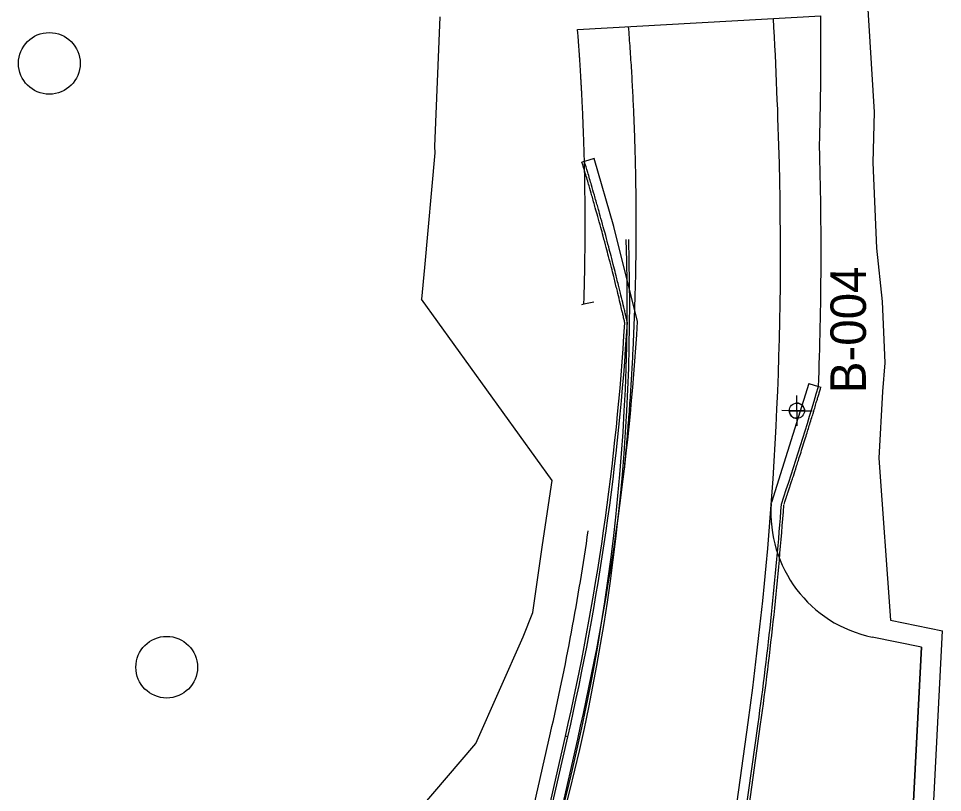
# Model space of a CAD drawing. Extents: x -14 to 1565148, y -25 to 642856.
# Drawn here: x 1564634.8 to 1564817, y 636708.2 to 636860.8 of the extents above; entities that cross this region are included whole.
import ezdxf

# ---------------------------------------------------------------- set-up
doc = ezdxf.new("R2010")
doc.units = 0
for name, color, linetype in [('_CIVIL_CONSTRUCTION', 7, 'Continuous'), ('DR_P_Drainage_Area', 7, 'Continuous'), ('DR_P_Erosion_Control', 7, 'Continuous'), ('GE_P_Alignment', 7, 'Continuous'), ('GE_X_Alignment', 7, 'Continuous'), ('PM_X_CL_Double_Solid', 7, 'Continuous'), ('PV_P_EOP', 7, 'Continuous'), ('PV_X_COP', 7, 'Continuous'), ('PV_X_EOP', 7, 'Continuous'), ('SC_Scratch10', 7, 'Continuous'), ('SC_Scratch15', 7, 'Continuous'), ('SC_Scratch2', 7, 'Continuous'), ('VG_P_Text', 7, 'Continuous')]:
    doc.layers.add(name, color=color, linetype=linetype)

msp = doc.modelspace()

# ---------------------------------------------------------------- linework, layer by layer
at = {"layer": '_CIVIL_CONSTRUCTION'}
for p, q in [((1564788.32, 636783.45), (1564788.33, 636786.45)), ((1564788.32, 636783.45), (1564788.32, 636784.95)), ((1564788.32, 636783.45), (1564785.32, 636783.46)), ((1564786.82, 636783.45), (1564788.32, 636783.45)), ((1564788.32, 636783.45), (1564791.32, 636783.45)), ((1564788.32, 636783.45), (1564788.32, 636780.45)), ((1564789.82, 636783.45), (1564788.32, 636783.45)), ((1564788.32, 636783.45), (1564788.32, 636781.95))]:
    msp.add_line(p, q, dxfattribs=at)
msp.add_circle((1564788.32, 636783.45), 1.5, dxfattribs=at)
for start, end in [(359.94, 89.94), (179.94, 269.94)]:
    msp.add_arc((1564788.32, 636783.45), 1.5, start, end, dxfattribs=at)
at = {"layer": 'DR_P_Drainage_Area'}
for radius in [397.5, 398]:
    msp.add_arc((1564357.36, 636804.71), radius, 342.3578, 1.7978, dxfattribs=at)
at = {"layer": 'DR_P_Erosion_Control'}
msp.add_open_spline([(1564754.31, 636771.87), (1564754.45, 636773.32), (1564754.72, 636776.23), (1564755.08, 636780.59), (1564755.41, 636784.95), (1564755.7, 636789.32), (1564755.95, 636793.69), (1564756.16, 636798.06), (1564756.33, 636802.43), (1564756.47, 636806.8), (1564756.57, 636811.17), (1564756.63, 636815.55), (1564756.65, 636819.92), (1564756.64, 636824.29), (1564756.58, 636828.66), (1564756.49, 636833.02), (1564756.36, 636837.39), (1564756.2, 636841.75), (1564755.99, 636846.11), (1564755.75, 636850.47), (1564755.47, 636854.83), (1564755.25, 636857.73), (1564755.14, 636859.18)], degree=3, dxfattribs=at)
at = {"layer": 'GE_P_Alignment'}
msp.add_arc((1564110.09, 636814.7), 683, 357.77768, 1.74215, dxfattribs=at)
for points in [[(1564792.77, 636835.46), (1564792.79, 636835.89), (1564792.81, 636836.75), (1564792.85, 636838.04), (1564792.88, 636839.33), (1564792.91, 636840.62), (1564792.93, 636841.91), (1564792.96, 636843.2), (1564792.98, 636844.5), (1564793, 636845.79), (1564793.02, 636847.08), (1564793.03, 636848.37), (1564793.05, 636849.66), (1564793.06, 636850.95), (1564793.07, 636852.24), (1564793.07, 636853.53), (1564793.07, 636854.83), (1564793.07, 636856.12), (1564793.07, 636857.41), (1564793.07, 636858.7), (1564793.06, 636859.99), (1564793.06, 636860.85), (1564793.05, 636861.29)], [(1564746.42, 636832.6), (1564746.39, 636834.11), (1564746.34, 636835.57), (1564746.26, 636837.91), (1564746.23, 636838.8), (1564746.16, 636840.59), (1564746.12, 636841.48), (1564746.04, 636843.26), (1564746, 636844.15), (1564745.93, 636845.49), (1564745.91, 636845.93), (1564745.86, 636846.83), (1564745.82, 636847.72), (1564745.76, 636848.61), (1564745.71, 636849.5), (1564745.69, 636849.95), (1564745.61, 636851.28), (1564745.55, 636852.17), (1564745.47, 636853.28), (1564745.46, 636853.5), (1564745.43, 636853.95), (1564745.41, 636854.17), (1564745.37, 636854.83), (1564745.34, 636855.28), (1564745.24, 636856.62), (1564745.17, 636857.52), (1564745.09, 636858.62)]]:
    msp.add_open_spline(points, degree=3, dxfattribs=at)
at = {"layer": 'GE_X_Alignment'}
msp.add_lwpolyline([(1564800.19, 636706.05), (1564811.23, 636705.19), (1564812.86, 636736.84), (1564811.23, 636705.19), (1564800.19, 636706.05)], dxfattribs=at)
at = {"layer": 'PM_X_CL_Double_Solid'}
for p, q in [((1564746.32, 636804.45), (1564745.83, 636804.34)), ((1564748.28, 636804.85), (1564746.32, 636804.45))]:
    msp.add_line(p, q, dxfattribs=at)
msp.add_open_spline([(1564746.32, 636804.45), (1564746.32, 636804.6), (1564746.33, 636804.74), (1564746.45, 636808.46), (1564746.52, 636812.03), (1564746.59, 636819.17), (1564746.58, 636822.74), (1564746.51, 636828.41), (1564746.47, 636830.51), (1564746.42, 636832.6)], degree=3, dxfattribs=at)
at = {"layer": 'PV_P_EOP'}
for p, q in [((1564746.42, 636832.6), (1564745.94, 636832.46)), ((1564792.58, 636788.22), (1564793.06, 636788.07)), ((1564773.12, 636667.28), (1564780.67, 636721.69)), ((1564778.16, 636699.96), (1564781.17, 636721.62)), ((1564731.52, 636670.52), (1564742.67, 636719.26)), ((1564732.01, 636670.41), (1564743.16, 636719.15))]:
    msp.add_line(p, q, dxfattribs=at)
for centre, radius, start, end in [((1564252.82, 636831.29), 502.5, 347.1178, 356.5174), ((1564252.82, 636831.29), 503, 347.1178, 356.5263), ((1564144.31, 636979.68), 675.95, 341.48255, 343.54567), ((1564110.09, 636814.7), 677, 352.10361, 355.79015), ((1564110.09, 636814.7), 677.5, 352.10361, 355.77956)]:
    msp.add_arc(centre, radius, start, end, dxfattribs=at)
for points in [[(1564754.4, 636800.77), (1564754.37, 636800.89), (1564754.32, 636801.12), (1564754.2, 636801.63), (1564754.13, 636801.92), (1564753.92, 636802.83), (1564753.75, 636803.53), (1564753.23, 636805.72), (1564752.84, 636807.31), (1564752.13, 636810.17), (1564751.81, 636811.44), (1564751.14, 636814.04), (1564750.79, 636815.38), (1564750.08, 636818.05), (1564749.71, 636819.39), (1564749, 636821.97), (1564748.65, 636823.21), (1564747.85, 636826.03), (1564747.4, 636827.59), (1564746.56, 636830.44), (1564746.17, 636831.72), (1564745.94, 636832.46)], [(1564754.9, 636800.82), (1564754.87, 636800.94), (1564754.85, 636801.03), (1564754.8, 636801.24), (1564754.77, 636801.36), (1564754.68, 636801.75), (1564754.62, 636802.03), (1564754.4, 636802.95), (1564754.24, 636803.64), (1564753.72, 636805.84), (1564753.33, 636807.43), (1564752.62, 636810.29), (1564752.3, 636811.56), (1564751.62, 636814.17), (1564751.27, 636815.51), (1564750.56, 636818.18), (1564750.2, 636819.52), (1564749.48, 636822.1), (1564749.13, 636823.35), (1564748.33, 636826.16), (1564747.88, 636827.73), (1564747.04, 636830.58), (1564746.65, 636831.86), (1564746.42, 636832.6)], [(1564785.78, 636764.96), (1564785.86, 636765.2), (1564785.94, 636765.44), (1564786.1, 636765.92), (1564786.18, 636766.16), (1564786.42, 636766.88), (1564786.57, 636767.36), (1564786.89, 636768.32), (1564787.05, 636768.8), (1564787.36, 636769.76), (1564787.52, 636770.24), (1564788.3, 636772.64), (1564788.91, 636774.56), (1564790.13, 636778.41), (1564790.72, 636780.34), (1564791.61, 636783.24), (1564791.9, 636784.2), (1564792.26, 636785.41), (1564792.34, 636785.65), (1564792.48, 636786.14), (1564792.55, 636786.38), (1564792.7, 636786.86), (1564792.77, 636787.11), (1564792.91, 636787.59), (1564792.98, 636787.83), (1564793.06, 636788.07)]]:
    msp.add_open_spline(points, degree=3, dxfattribs=at)
at = {"layer": 'PV_X_COP'}
for p, q in [((1564812.86, 636736.84), (1564803.18, 636738.82)), ((1564811.23, 636705.19), (1564812.86, 636736.84))]:
    msp.add_line(p, q, dxfattribs=at)
msp.add_arc((1564808.2, 636763.31), 25, 175.7902, 258.4067, dxfattribs=at)
at = {"layer": 'PV_X_EOP'}
for p, q in [((1564745.09, 636858.62), (1564793.05, 636861.29)), ((1564748.34, 636833.16), (1564746.42, 636832.6)), ((1564790.67, 636788.82), (1564783.29, 636765.38)), ((1564790.67, 636788.82), (1564792.58, 636788.22)), ((1564771.14, 636667.56), (1564778.69, 636721.97)), ((1564733.96, 636669.96), (1564745.11, 636718.7))]:
    msp.add_line(p, q, dxfattribs=at)
msp.add_lwpolyline([(1564756.91, 636801.02), (1564752.21, 636819.74), (1564748.34, 636833.16)], dxfattribs=at)
for centre, radius, start, end in [((1563817.53, 636807.13), 967.66, 1.4827, 3.17756), ((1564110.09, 636814.7), 675, 352.10361, 1.4827), ((1564252.82, 636831.29), 505, 347.1178, 356.5636)]:
    msp.add_arc(centre, radius, start, end, dxfattribs=at)
at = {"layer": 'SC_Scratch10'}
msp.add_line((1564728.6, 636671.19), (1564739.75, 636719.93), dxfattribs=at)
msp.add_arc((1564252.09, 636831.46), 500.25, 347.1178, 351.7606, dxfattribs=at)
at = {"layer": 'SC_Scratch15'}
msp.add_line((1564743.16, 636719.15), (1564742.67, 636719.26), dxfattribs=at)
at = {"layer": 'SC_Scratch2'}
for p, q in [((1564804.49, 636774.07), (1564806.79, 636742.17)), ((1564806.79, 636742.17), (1564817.03, 636740.06)), ((1564815.02, 636700.89), (1564817.03, 636740.06))]:
    msp.add_line(p, q, dxfattribs=at)
for points in [[(1564802.1, 636865.85), (1564803.55, 636842.29), (1564803.31, 636832.4), (1564803.99, 636815.48), (1564805.11, 636805), (1564805.66, 636792.9), (1564805.18, 636787.22), (1564804.49, 636774.07)], [(1564717.91, 636861.1), (1564716.85, 636835.54), (1564716.95, 636834.29), (1564714.9, 636811.7), (1564714.31, 636805.46)], [(1564704.93, 636688.71), (1564706.33, 636691.63), (1564713.87, 636704.78), (1564725.03, 636717.86), (1564734.35, 636738.84), (1564736.25, 636743.65), (1564738.19, 636757.02), (1564740.07, 636769.72), (1564714.31, 636805.46)]]:
    msp.add_lwpolyline(points, dxfattribs=at)
at = {"layer": 'VG_P_Text'}
for centre in [(1564640.92, 636851.92), (1564664.06, 636732.88)]:
    msp.add_circle(centre, 6.08, dxfattribs=at)

# ---------------------------------------------------------------- texts
msp.add_text('B-004', height=7, rotation=89.94, dxfattribs=at).set_placement((1564801.92, 636786.89))

doc.saveas('drawing.dxf')
